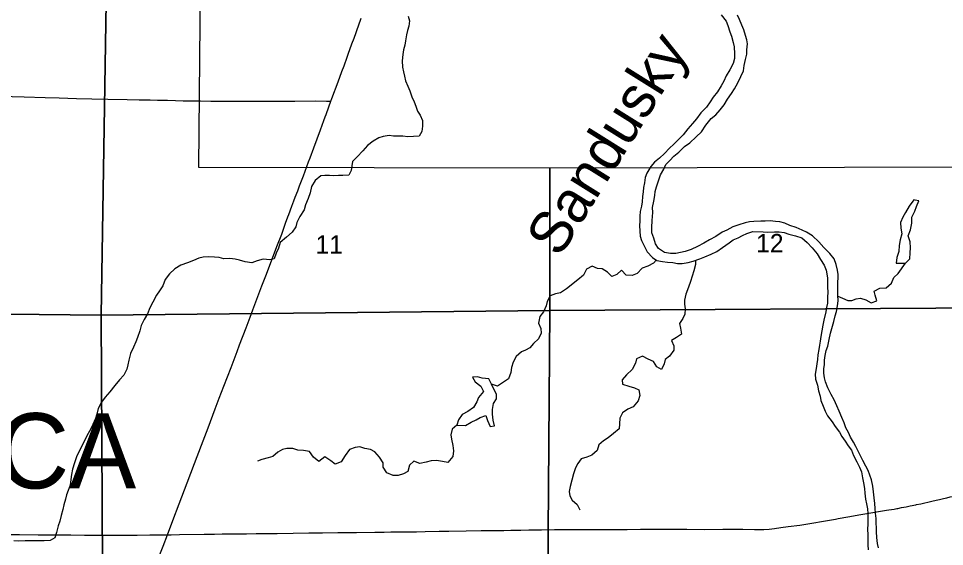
# Model space of a CAD drawing. Extents: x 0 to 34, y 0 to 22.
# Drawn here: x 4.352 to 5.402, y 16.136 to 16.734 of the extents above; entities that cross this region are included whole.
import ezdxf

# ---------------------------------------------------------------- set-up
doc = ezdxf.new("R2010")
doc.units = 0
for name, color, linetype in [('GM_X_County_Road', 7, 'Continuous'), ('GM_X_Major_River', 7, 'Continuous'), ('GM_X_Major_River_Text', 7, 'Continuous'), ('GM_X_Minor_Lake', 7, 'Continuous'), ('GM_X_Minor_River', 7, 'Continuous'), ('GM_X_Section', 7, 'Continuous'), ('GM_X_Section_Text', 7, 'Continuous'), ('GM_X_State_Route', 7, 'Continuous'), ('GM_X_Township_Road', 7, 'Continuous'), ('GM_X_Township_Text', 7, 'Continuous')]:
    doc.layers.add(name, color=color, linetype=linetype)

msp = doc.modelspace()

# ---------------------------------------------------------------- linework, layer by layer
at = {"layer": 'GM_X_County_Road'}
for points in [[(5.3697, 16.1827), (5.3704, 16.1829), (5.3755, 16.184), (5.3879, 16.1868), (5.3927, 16.1879), (5.3966, 16.1889), (5.4012, 16.1899), (5.4051, 16.1907), (5.4087, 16.1916), (5.4118, 16.1921), (5.4148, 16.1925), (5.4173, 16.1928), (5.4208, 16.1928), (5.4339, 16.1926), (5.4514, 16.1921), (5.4547, 16.192)], [(5.2816, 16.1671), (5.2928, 16.1691), (5.3074, 16.1716), (5.3365, 16.1765), (5.3393, 16.1769), (5.3451, 16.1779), (5.3484, 16.1786), (5.3493, 16.1787), (5.3536, 16.1795), (5.3588, 16.1804), (5.3634, 16.1814), (5.3697, 16.1827)], [(4.5208, 16.1489), (4.5249, 16.1489), (4.5346, 16.149), (4.5625, 16.1493), (4.5743, 16.1496), (4.583, 16.1497), (4.6005, 16.1497), (4.6104, 16.1499), (4.6216, 16.1501), (4.6306, 16.1502), (4.6452, 16.1503), (4.6635, 16.1506), (4.6813, 16.1509), (4.6968, 16.1509), (4.7142, 16.1512), (4.7353, 16.1515), (4.7562, 16.1517), (4.7667, 16.1519), (4.7742, 16.152), (4.7857, 16.1521), (4.8034, 16.1523), (4.8133, 16.1525), (4.8289, 16.1527), (4.84, 16.153), (4.8596, 16.1533), (4.8767, 16.1535), (4.8907, 16.1537), (4.9025, 16.1538), (4.9103, 16.1539), (4.9168, 16.1541), (4.9217, 16.1541), (4.9307, 16.1543), (4.9354, 16.1544), (4.9453, 16.1545), (4.9599, 16.1546), (4.9752, 16.1547), (4.9913, 16.1547), (5.0103, 16.1548), (5.0258, 16.1547), (5.0423, 16.1548), (5.0575, 16.155), (5.0709, 16.155), (5.0958, 16.155), (5.11, 16.155), (5.1299, 16.1549), (5.1508, 16.155), (5.1548, 16.155), (5.1573, 16.155), (5.1666, 16.155), (5.1734, 16.155), (5.1868, 16.1548), (5.193, 16.1548), (5.1973, 16.1549), (5.2035, 16.1553), (5.2094, 16.1559), (5.2165, 16.1569), (5.2251, 16.1581), (5.2381, 16.1598), (5.2785, 16.1666), (5.2816, 16.1671)]]:
    msp.add_lwpolyline(points, dxfattribs=at)
at = {"layer": 'GM_X_Major_River'}
for points in [[(5.1008, 16.5825), (5.1073, 16.5887), (5.1134, 16.5928), (5.1205, 16.5996), (5.1266, 16.6052), (5.1314, 16.6128), (5.1375, 16.6203), (5.1429, 16.6248), (5.1478, 16.6301), (5.1524, 16.6358), (5.1563, 16.6422), (5.1605, 16.6488), (5.1639, 16.6539), (5.1678, 16.6607), (5.1714, 16.6681), (5.1743, 16.6745), (5.1751, 16.6804), (5.1767, 16.6874), (5.1779, 16.6934), (5.1781, 16.6982), (5.1789, 16.705), (5.1782, 16.7097), (5.1767, 16.7147), (5.1747, 16.7211), (5.1724, 16.7263), (5.1698, 16.7328), (5.1676, 16.7375)], [(5.149, 16.7378), (5.1545, 16.7308), (5.1565, 16.726), (5.1587, 16.7188), (5.1606, 16.7137), (5.1626, 16.7066), (5.1637, 16.7015), (5.1642, 16.6937), (5.164, 16.6886), (5.1624, 16.6827), (5.1586, 16.6756), (5.1548, 16.6689), (5.1519, 16.6629), (5.149, 16.6574), (5.1449, 16.6508), (5.14, 16.6446), (5.1365, 16.6395)], [(5.1365, 16.6395), (5.1323, 16.6334), (5.126, 16.6267), (5.1208, 16.6201), (5.1166, 16.6148), (5.1112, 16.6089), (5.1059, 16.602), (5.1011, 16.5969), (5.0952, 16.5912), (5.0902, 16.5869), (5.0848, 16.5807), (5.0789, 16.5754), (5.0732, 16.5711), (5.0692, 16.5662), (5.0648, 16.5587), (5.0626, 16.5535), (5.0618, 16.5477), (5.061, 16.5424), (5.0604, 16.5372), (5.0596, 16.5319), (5.0592, 16.5261), (5.0586, 16.5211), (5.0572, 16.5151), (5.0568, 16.5098), (5.0568, 16.5043), (5.0563, 16.4993), (5.0565, 16.4927), (5.0572, 16.487), (5.0585, 16.4823), (5.0615, 16.4763), (5.065, 16.4693), (5.0711, 16.463), (5.076, 16.4597), (5.0824, 16.4584), (5.0879, 16.4576), (5.0942, 16.4573), (5.0993, 16.4563), (5.1048, 16.4561), (5.1114, 16.4572), (5.1171, 16.4589), (5.1249, 16.4613), (5.1303, 16.4637), (5.1377, 16.4667), (5.144, 16.4698), (5.1503, 16.4743), (5.1579, 16.4794), (5.1627, 16.483), (5.1682, 16.4852), (5.173, 16.4878), (5.1781, 16.4901), (5.1847, 16.4925), (5.1965, 16.492), (5.2018, 16.4918), (5.2094, 16.4919), (5.2147, 16.4919), (5.2204, 16.4913), (5.2257, 16.4895), (5.2331, 16.4876), (5.2403, 16.4852), (5.2465, 16.4801), (5.252, 16.474), (5.258, 16.4671), (5.2615, 16.4606), (5.2657, 16.4541), (5.2679, 16.4486), (5.2697, 16.4401), (5.2695, 16.4351), (5.2695, 16.4294), (5.2698, 16.4236), (5.2696, 16.4181), (5.2695, 16.4114), (5.2684, 16.4063), (5.2676, 16.4014), (5.2656, 16.3919), (5.2644, 16.3864), (5.262, 16.3735), (5.2612, 16.3682), (5.2606, 16.3635), (5.2597, 16.3586), (5.2585, 16.3527), (5.2584, 16.3474), (5.2576, 16.3423), (5.2567, 16.3373), (5.2557, 16.3309), (5.2558, 16.325), (5.2582, 16.3184), (5.2595, 16.3117), (5.2612, 16.306), (5.2621, 16.3009), (5.2647, 16.2944), (5.2669, 16.2887), (5.2697, 16.2836), (5.275, 16.2767), (5.2784, 16.2713), (5.2831, 16.2651), (5.2857, 16.2603), (5.2896, 16.2549), (5.2932, 16.2496), (5.2968, 16.2446), (5.2992, 16.2387), (5.3027, 16.2313)], [(5.3256, 16.1456), (5.3253, 16.1522), (5.3251, 16.157), (5.3246, 16.1617), (5.3247, 16.1674), (5.3241, 16.1731), (5.3238, 16.1784), (5.3231, 16.1843), (5.3224, 16.1906), (5.3217, 16.1976), (5.3209, 16.2039), (5.3195, 16.2111), (5.3176, 16.2162), (5.3156, 16.2217), (5.3129, 16.2265), (5.3096, 16.2328), (5.3017, 16.2488), (5.2989, 16.2539), (5.2957, 16.2595), (5.2933, 16.2646), (5.2905, 16.2701), (5.2885, 16.2758), (5.286, 16.2817), (5.283, 16.2888), (5.2802, 16.295), (5.2771, 16.3017), (5.2737, 16.3078), (5.27, 16.3152), (5.2672, 16.3219), (5.2661, 16.3268), (5.2653, 16.3318), (5.2656, 16.3369), (5.266, 16.3416), (5.2662, 16.3466), (5.2668, 16.3519), (5.268, 16.3574), (5.2699, 16.3625), (5.2715, 16.37), (5.2731, 16.3771), (5.2766, 16.3903), (5.2783, 16.3967), (5.2797, 16.4019), (5.2811, 16.4083), (5.2815, 16.4138), (5.2814, 16.4202), (5.2812, 16.4256), (5.2814, 16.4314), (5.2815, 16.4438), (5.2808, 16.4487), (5.2793, 16.4552), (5.2771, 16.4614), (5.2722, 16.4675), (5.2654, 16.4744), (5.2598, 16.4809), (5.2526, 16.4874), (5.2458, 16.4918), (5.2407, 16.494), (5.2339, 16.4969), (5.2269, 16.4994), (5.2212, 16.5019), (5.2154, 16.5033), (5.2106, 16.5039), (5.2044, 16.5045), (5.1989, 16.5043), (5.1938, 16.504), (5.186, 16.5039), (5.181, 16.5035), (5.1761, 16.5022), (5.1691, 16.4998), (5.1622, 16.4976), (5.1552, 16.494), (5.1502, 16.4916), (5.143, 16.4869), (5.1357, 16.4828), (5.1291, 16.4791), (5.122, 16.4753), (5.115, 16.472), (5.1083, 16.4699), (5.103, 16.4686), (5.0975, 16.4675), (5.0914, 16.4676), (5.0846, 16.4686), (5.078, 16.473), (5.0744, 16.4783), (5.0724, 16.4848), (5.0703, 16.4911), (5.0704, 16.497), (5.0708, 16.5047), (5.0713, 16.514), (5.0711, 16.5195), (5.0725, 16.5269), (5.0737, 16.5332), (5.0741, 16.5379), (5.0755, 16.543), (5.078, 16.55), (5.0801, 16.5568), (5.0838, 16.5629), (5.0861, 16.5684), (5.0909, 16.5727), (5.0951, 16.5776), (5.1008, 16.5825)], [(5.3027, 16.2313), (5.3059, 16.2252), (5.308, 16.2201), (5.3094, 16.2133), (5.3105, 16.2076), (5.3114, 16.2011), (5.312, 16.196), (5.3127, 16.1893), (5.314, 16.1838), (5.3149, 16.1781), (5.3152, 16.173), (5.3154, 16.1663), (5.3153, 16.1612), (5.3151, 16.1548), (5.3154, 16.1491), (5.3154, 16.1438), (5.3155, 16.1373), (5.3159, 16.1318)], [(5.3274, 16.1338), (5.3262, 16.1389), (5.3256, 16.1456)]]:
    msp.add_lwpolyline(points, dxfattribs=at)
at = {"layer": 'GM_X_Minor_Lake'}
for points in [[(5.3692, 16.528), (5.3675, 16.5283), (5.3624, 16.5213), (5.3579, 16.5141), (5.3549, 16.5088), (5.3525, 16.5026), (5.3529, 16.4962), (5.3538, 16.4899), (5.352, 16.4829), (5.351, 16.4764), (5.3504, 16.4696), (5.3481, 16.463), (5.3473, 16.4564), (5.3581, 16.4565)], [(5.3581, 16.4565), (5.3631, 16.4615), (5.3635, 16.4682), (5.3637, 16.4739), (5.3632, 16.4807), (5.3612, 16.4877), (5.3637, 16.4944), (5.3654, 16.5017), (5.3653, 16.5088), (5.3688, 16.5156), (5.3705, 16.5207), (5.373, 16.5273), (5.3692, 16.528)], [(4.8886, 16.3193), (4.8853, 16.3253), (4.8779, 16.3262), (4.8727, 16.3277), (4.8667, 16.3272), (4.87, 16.3222), (4.8763, 16.3171), (4.8795, 16.311), (4.8735, 16.3042), (4.8716, 16.2993), (4.8681, 16.293), (4.8615, 16.2885), (4.8552, 16.2852), (4.8511, 16.2791), (4.8492, 16.2731)], [(4.8492, 16.2731), (4.8589, 16.2726), (4.8655, 16.2764), (4.8709, 16.279), (4.8756, 16.2818), (4.8821, 16.284), (4.884, 16.2781), (4.8869, 16.2713), (4.8919, 16.2724), (4.8904, 16.2786), (4.8895, 16.2853), (4.8897, 16.2906), (4.8905, 16.2976), (4.894, 16.3029), (4.8942, 16.3078), (4.8886, 16.3193)]]:
    msp.add_lwpolyline(points, dxfattribs=at)
at = {"layer": 'GM_X_Minor_River'}
for points in [[(4.7938, 16.7363), (4.7955, 16.731), (4.7945, 16.7251), (4.7933, 16.72), (4.7919, 16.7151), (4.7908, 16.7085), (4.79, 16.7036), (4.7886, 16.6981), (4.7878, 16.6928), (4.7872, 16.6857), (4.7875, 16.6787), (4.7886, 16.6734), (4.7897, 16.6685), (4.791, 16.6633), (4.7934, 16.6571), (4.7958, 16.6517), (4.7981, 16.6449), (4.8005, 16.6394), (4.8025, 16.6346), (4.8044, 16.6289), (4.8074, 16.6241), (4.8102, 16.6182), (4.8103, 16.6116), (4.8092, 16.6059), (4.8065, 16.6006), (4.8, 16.5999), (4.7934, 16.5996), (4.7879, 16.6004), (4.7772, 16.6005), (4.7725, 16.6011), (4.7655, 16.6002), (4.7607, 16.5985), (4.7541, 16.5949), (4.7476, 16.5897), (4.7424, 16.5837), (4.7361, 16.5771), (4.7309, 16.5716), (4.7299, 16.5667), (4.7293, 16.5617), (4.7266, 16.5563), (4.7198, 16.5558), (4.7149, 16.5558), (4.7096, 16.5556), (4.7048, 16.5557), (4.6995, 16.5559), (4.6948, 16.5556), (4.6885, 16.5501), (4.6842, 16.5433), (4.6827, 16.5363), (4.6805, 16.5297), (4.6774, 16.5225), (4.6759, 16.5168), (4.6709, 16.5096), (4.6676, 16.5028), (4.6666, 16.4979), (4.6622, 16.4917), (4.6557, 16.486), (4.6488, 16.4798), (4.6467, 16.4734), (4.644, 16.4679), (4.6417, 16.4613), (4.6369, 16.4604), (4.6295, 16.461), (4.6227, 16.459), (4.6164, 16.4571), (4.609, 16.4579), (4.6024, 16.4601), (4.5975, 16.4609), (4.5914, 16.4617), (4.5848, 16.4615), (4.5795, 16.4629), (4.5742, 16.4635), (4.5675, 16.4639), (4.5613, 16.4634), (4.5565, 16.4623), (4.5504, 16.4595), (4.5434, 16.4569), (4.5358, 16.4543), (4.5291, 16.45), (4.523, 16.4444), (4.5184, 16.4381), (4.5157, 16.431), (4.5118, 16.4253), (4.5082, 16.4204), (4.5043, 16.4123), (4.5009, 16.406), (4.498, 16.3992)], [(5.0754, 16.4601), (5.0722, 16.4567), (5.0659, 16.4532), (5.0592, 16.4509), (5.0537, 16.4449), (5.0478, 16.4425), (5.0411, 16.4431), (5.0357, 16.4487), (5.0307, 16.4436), (5.025, 16.4413), (5.0199, 16.4463), (5.0139, 16.4501), (5.0087, 16.4504), (5.0027, 16.4531), (4.9962, 16.4497), (4.9926, 16.4429), (4.9865, 16.4378), (4.9735, 16.4273), (4.9668, 16.4228), (4.9609, 16.4219), (4.9548, 16.4195), (4.9515, 16.4132), (4.9504, 16.4081), (4.9475, 16.4015), (4.9433, 16.396), (4.9417, 16.3887), (4.9443, 16.3826), (4.9448, 16.3774), (4.9416, 16.3708), (4.9362, 16.3654), (4.9318, 16.3605), (4.927, 16.3579), (4.9223, 16.3562), (4.9164, 16.3509), (4.9129, 16.3445), (4.9112, 16.3384), (4.9105, 16.3326), (4.9076, 16.3256), (4.8951, 16.3173), (4.8886, 16.3193), (4.8853, 16.3253), (4.8779, 16.3262), (4.8727, 16.3277), (4.8667, 16.3272), (4.87, 16.3222), (4.8763, 16.3171), (4.8795, 16.311), (4.8735, 16.3042), (4.8716, 16.2993), (4.8681, 16.293), (4.8615, 16.2885), (4.8552, 16.2852), (4.8511, 16.2791), (4.8492, 16.2731), (4.8437, 16.2684), (4.8423, 16.2619), (4.843, 16.2572), (4.8447, 16.2498), (4.8454, 16.2439), (4.8446, 16.2373), (4.839, 16.2308), (4.8328, 16.2318), (4.8259, 16.2328), (4.8199, 16.2325), (4.8142, 16.2312), (4.8071, 16.2296), (4.8003, 16.2321), (4.7954, 16.2278), (4.7934, 16.2204), (4.7885, 16.2178), (4.7827, 16.2161), (4.7769, 16.2158), (4.7695, 16.2188), (4.7656, 16.2253), (4.7656, 16.2304), (4.7613, 16.2369), (4.756, 16.2427), (4.7511, 16.2454), (4.7448, 16.2467), (4.7392, 16.2483), (4.7337, 16.2478), (4.7272, 16.2455), (4.7224, 16.2387), (4.718, 16.2314), (4.7109, 16.2288), (4.706, 16.2326), (4.6994, 16.2372), (4.6927, 16.2319), (4.6865, 16.2367), (4.682, 16.2432), (4.6752, 16.2442), (4.6687, 16.2448), (4.6631, 16.2464), (4.6564, 16.2466), (4.6515, 16.2455), (4.646, 16.2422), (4.6402, 16.2373), (4.6351, 16.2358), (4.6279, 16.2341), (4.6231, 16.2323)], [(5.1198, 16.4597), (5.1198, 16.4549), (5.1178, 16.4478), (5.1161, 16.4418), (5.1141, 16.4359), (5.112, 16.4293), (5.1087, 16.4214), (5.1073, 16.4147), (5.1075, 16.41), (5.108, 16.4049), (5.1076, 16.3988), (5.1055, 16.3939), (5.1018, 16.388), (5.1029, 16.3829), (5.104, 16.3761), (5.0983, 16.3725), (5.0926, 16.3691), (5.0954, 16.3627), (5.0953, 16.3579), (5.0902, 16.3513), (5.0854, 16.3475), (5.0842, 16.3424), (5.0813, 16.3362), (5.0758, 16.3389), (5.0721, 16.3452), (5.0662, 16.3477), (5.0596, 16.351), (5.053, 16.348), (5.0518, 16.3431), (5.0479, 16.3359), (5.0416, 16.3302), (5.0368, 16.3244), (5.0372, 16.3195), (5.0442, 16.3171), (5.0506, 16.3152), (5.0555, 16.3131), (5.0568, 16.3066), (5.0547, 16.3007), (5.0493, 16.2939), (5.0432, 16.291), (5.0369, 16.2868), (5.0339, 16.2808), (5.0336, 16.2745), (5.0332, 16.2688), (5.0267, 16.2636), (5.0206, 16.2585), (5.0155, 16.2551), (5.0101, 16.2506), (5.0082, 16.2444), (5.0023, 16.2389), (4.9965, 16.2367), (4.9901, 16.235), (4.9862, 16.2297), (4.9837, 16.2246), (4.9816, 16.218), (4.9795, 16.2106), (4.9777, 16.2036), (4.9767, 16.1977), (4.9771, 16.193), (4.9799, 16.1879), (4.9855, 16.1829), (4.9885, 16.177)], [(5.2814, 16.4192), (5.2865, 16.4168), (5.2925, 16.4143), (5.2973, 16.4144), (5.3022, 16.4161), (5.3069, 16.417), (5.313, 16.4149), (5.3191, 16.4116), (5.3255, 16.4138), (5.3235, 16.4201), (5.3224, 16.4249), (5.329, 16.4284), (5.3361, 16.4286), (5.3422, 16.4338), (5.3449, 16.4403), (5.3498, 16.4448), (5.3581, 16.4565)], [(4.498, 16.3992), (4.4943, 16.3928), (4.4909, 16.386), (4.4893, 16.3799), (4.4868, 16.3724), (4.485, 16.3674), (4.4823, 16.3612), (4.4787, 16.354), (4.4769, 16.3468), (4.4759, 16.3413), (4.4746, 16.3364), (4.4715, 16.3296), (4.4663, 16.3243), (4.4611, 16.3179), (4.4556, 16.3109), (4.4502, 16.3047), (4.446, 16.2992), (4.4422, 16.2919), (4.4408, 16.2854), (4.4392, 16.2805), (4.4363, 16.2737), (4.4338, 16.2688), (4.4308, 16.2635), (4.4271, 16.2565), (4.424, 16.2501), (4.4208, 16.2435), (4.4177, 16.237), (4.4153, 16.2302), (4.413, 16.2232), (4.4118, 16.217), (4.4112, 16.2113), (4.4104, 16.205), (4.4081, 16.199), (4.4063, 16.1941), (4.405, 16.1891), (4.4034, 16.1827), (4.4021, 16.1776), (4.4001, 16.1706), (4.3987, 16.1641), (4.397, 16.1588), (4.3948, 16.1515), (4.3931, 16.1454), (4.3876, 16.1424), (4.3809, 16.1419), (4.3712, 16.142), (4.3661, 16.1418), (4.3595, 16.1419), (4.3523, 16.1417), (4.3466, 16.1418)]]:
    msp.add_lwpolyline(points, dxfattribs=at)
at = {"layer": 'GM_X_Section'}
for points in [[(3.9597, 16.903), (4.4534, 16.894), (4.4457, 16.3978), (3.9537, 16.4029)], [(4.4534, 16.894), (4.5591, 16.8926), (4.5561, 16.5652), (4.9547, 16.5647), (4.9544, 16.4029), (4.4457, 16.3978)], [(5.456, 16.5658), (5.455, 16.4061), (4.9544, 16.4029), (4.9547, 16.5647)], [(4.4457, 16.3978), (4.4483, 15.8978), (3.9457, 15.9014), (3.9537, 16.4029)], [(4.9544, 16.4029), (4.9508, 15.9008), (4.4483, 15.8978), (4.4457, 16.3978)], [(5.455, 16.4061), (5.4537, 15.9057), (4.9508, 15.9008), (4.9544, 16.4029)]]:
    msp.add_lwpolyline(points, close=True, dxfattribs=at)
at = {"layer": 'GM_X_State_Route'}
msp.add_lwpolyline([(4.5114, 16.1244), (4.5159, 16.136), (4.5208, 16.1488), (4.5208, 16.1489), (4.5268, 16.1648), (4.534, 16.184), (4.5433, 16.2077), (4.5515, 16.2296), (4.5593, 16.2502), (4.5669, 16.2699), (4.5749, 16.2915), (4.5796, 16.3036), (4.5848, 16.317), (4.5929, 16.3385), (4.5975, 16.3504), (4.5998, 16.3565), (4.6026, 16.364), (4.61, 16.3832), (4.6147, 16.3954), (4.6178, 16.4038), (4.628, 16.4309), (4.633, 16.4439), (4.645, 16.4753), (4.6505, 16.4895), (4.6549, 16.5018), (4.6575, 16.5091), (4.6585, 16.5117), (4.662, 16.521), (4.6643, 16.5271), (4.6658, 16.5312), (4.6686, 16.5385), (4.6706, 16.544), (4.6728, 16.5498), (4.675, 16.5556), (4.6808, 16.5714), (4.6826, 16.576), (4.6868, 16.5874), (4.6943, 16.6078), (4.6963, 16.613), (4.6982, 16.6183), (4.6997, 16.6224), (4.7007, 16.625), (4.7039, 16.6337), (4.7063, 16.6401), (4.7074, 16.643), (4.7144, 16.662), (4.7188, 16.6739), (4.7211, 16.6801), (4.7246, 16.69), (4.7259, 16.6935), (4.73, 16.7049), (4.7325, 16.7116), (4.7349, 16.718), (4.7361, 16.7215), (4.7374, 16.7253), (4.7407, 16.7341)], dxfattribs=at)
at = {"layer": 'GM_X_Township_Road'}
for points in [[(4.3307, 16.6457), (4.3581, 16.6449), (4.382, 16.6442), (4.3978, 16.6438), (4.4177, 16.6432), (4.4351, 16.6429), (4.4532, 16.6424), (4.4752, 16.642), (4.4886, 16.6417), (4.5013, 16.6415), (4.5097, 16.6413), (4.5209, 16.6411), (4.5299, 16.6408), (4.5386, 16.6406), (4.5535, 16.6405), (4.5582, 16.6404), (4.57, 16.6402), (4.584, 16.6401), (4.6017, 16.6401), (4.6169, 16.6402), (4.6284, 16.6402), (4.6465, 16.6402), (4.6654, 16.6402), (4.6891, 16.6404), (4.7012, 16.6402), (4.7063, 16.6401)], [(4.3276, 16.1492), (4.3531, 16.1491), (4.3743, 16.1489), (4.396, 16.1487), (4.4112, 16.1486), (4.4268, 16.1484), (4.4436, 16.1484), (4.4675, 16.1483), (4.4753, 16.1483), (4.4865, 16.1483), (4.5008, 16.1486), (4.5079, 16.1486), (4.5208, 16.1489)]]:
    msp.add_lwpolyline(points, dxfattribs=at)

# ---------------------------------------------------------------- texts
at = {"layer": 'GM_X_Major_River_Text'}
msp.add_text('Sandusky', height=0.04737, rotation=58.0061, dxfattribs=at).set_placement((4.9655, 16.4617))
at = {"layer": 'GM_X_Section_Text'}
for s, p in [('11', (4.6888, 16.4673)), ('12', (5.1886, 16.4687))]:
    msp.add_text(s, height=0.02093, rotation=0, dxfattribs=at).set_placement(p)
at = {"layer": 'GM_X_Township_Text'}
msp.add_text('SENECA', height=0.08523, rotation=0, dxfattribs=at).set_placement((4.0167, 16.2013))

doc.saveas('drawing.dxf')
